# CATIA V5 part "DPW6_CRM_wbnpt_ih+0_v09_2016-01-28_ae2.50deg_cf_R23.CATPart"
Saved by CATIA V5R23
Part number: DPW6_CRM_wbnpt_ih+0_v09_2016-01-28_ae2
Bounding box of the stored display mesh (mm): x 2349.5 to 66711.883, y -0.003 to 29452.59, z -66.045 to 8715.76
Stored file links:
  C:\Users\mrg\work\AIAA_DPW\DPW6\DLR_meshes\all\2deg50\DPW6_CRM_wbnpt_ih+0_v09_2016-01-28_ae2.50deg_cf.CATPart

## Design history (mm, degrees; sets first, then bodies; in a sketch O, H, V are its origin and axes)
MechanicalRefPlane1 "xy-plane"
MechanicalRefPlane2 "yz-plane"
MechanicalRefPlane3 "zx-plane"
Set1
  DatumSurface1 to DatumSurface3
Body1 (main body)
